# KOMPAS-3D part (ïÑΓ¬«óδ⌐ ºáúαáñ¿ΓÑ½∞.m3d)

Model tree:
1. Эскиз:1
2. Операция выдавливания:1
     Расстояние 1 = 2.7
3. Эскиз:2
4. Операция выдавливания:2
     Расстояние 1 = 3; Расстояние 2 = 3
5. Скругление:1
     Радиус = 1
6. Скругление:2  (labels: ā1Ā)
     Радиус = 0.5
